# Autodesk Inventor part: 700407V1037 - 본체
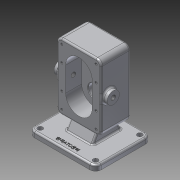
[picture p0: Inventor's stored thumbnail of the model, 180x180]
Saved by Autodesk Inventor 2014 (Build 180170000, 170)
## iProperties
Created: 2020-04
Part Number: 700407V1037 - 본체
Material: 알루미늄 6061
Document SubType Name: Modeling
Designer: kh
Density: 2.71 g/cm^3
Appearance: 알루미늄 - 평지
Mass: 1475.43 g
Surface Area: 815.025 cm^2
Volume: 544.438 cm^3
Author: kh
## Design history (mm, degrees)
sketch "스케치1"
  geometry: L1 (-50, 60)-(50, 60); L2 (50, 60)-(50, -60); L3 (50, -60)-(-50, -60); L4 (-50, -60)-(-50, 60); L5 (-50, 60)-(50, -60); L6 (50, 60)-(-50, -60); 1 further point
  constraints: 12 end point, 2 midpoint, 2 parallel, 1 horizontal, 1 perpendicular
  dimensions: "d0" = 100 distance of L2.end L3.end; "d1" = 120 distance of L1.end L2.end
extrude "돌출1" new body sketch "스케치1" stored distance "d2" = 10; taper "d3" = 0 deg
node "작업 평면2"
  node "작업 평면1"
sketch "스케치2"
  geometry: L1 (-120, 0)-(-120, -10) reference; L2 (0, 0)-(-120, 0) reference; L3 (0, 0)-(0, -10) reference; L4 (-120, -10)-(0, -10) reference; L5 (-100, 140)-(-20, 140); L6 (-20, 140)-(-20, 20); L7 (-20, 20)-(-100, 20); L8 (-100, 20)-(-100, 140); L9 (-20, 80)-(-100, 80); L10 (-60, 20)-(-60, 80); 1 further point
  constraints: 12 end point, 4 midpoint, 2 parallel, 1 horizontal, 1 perpendicular, 1 point on line
  dimensions: "d5" = 80 distance of L5.start L5.end; "d6" = 150 distance between parallel lines of L5 L4; "d7" = 90 distance between parallel lines of L9 L4
extrude "돌출2" join sketch "스케치2" distance "d8" = 53; taper "d9" = 0 deg
fillet "모깎기1" dims "d10" = 9
sketch "스케치4"
  geometry: L1 (20, 29)-(20, 91) reference; L2 (131, 20)-(29, 20) reference; L3 (140, 91)-(140, 29) reference; L4 (29, 100)-(131, 100) reference; L5 (102, 60)-(58, 60); L6 (102, 84)-(58, 84); L7 (58, 36)-(102, 36); L8 (20, 29)-(20, 91) reference; L9 (80, 100)-(80, 20); C1 r 12.5 at (102, 60); C2 r 12.5 at (58, 60); C3 r 8.5 at (102, 60); C4 r 8.5 at (58, 60); A1 r 9 centre (29, 91) between (29, 100) and (20, 91) reference; A2 r 9 centre (29, 29) between (20, 29) and (29, 20) reference; A3 r 9 centre (131, 29) between (131, 20) and (140, 29) reference; A4 r 9 centre (131, 91) between (140, 91) and (131, 100) reference; A5 r 24 centre (102, 60) between (102, 36) and (102, 84); A6 r 24 centre (58, 60) between (58, 84) and (58, 36); 3 further points
  constraints: 10 end point, 6 centre point, 5 coincident, 4 midpoint, 4 point on circle, 4 tangent, 1 parallel, 1 perpendicular
  dimensions: "d11" = 44 distance of L5.end L5.start; "d12" = 24 radius of A5; "d13" = 25 diameter of C1; "d14" = 25 diameter of C2; "d15" = 17 diameter of C3; "d16" = 17 diameter of C4
  node "투영된 루프5"
extrude "돌출3" cut sketch "스케치4" distance "d17" = 29; taper "d18" = 0 deg
extrude "돌출4" cut sketch "스케치4" distance "d19" = 44; taper "d20" = 0 deg
extrude "돌출5" cut sketch "스케치4" distance "d21" = 44; taper "d22" = 0 deg
sketch "스케치5"
  geometry: L1 (-29, 100)-(-131, 100) reference; L2 (-140, 91)-(-140, 29) reference; L3 (-131, 20)-(-29, 20) reference; L4 (-20, 29)-(-20, 91) reference; C1 r 8.5 at (-102, 60) reference; C2 r 14 at (-102, 60); C3 r 8.5 at (-102, 60); A1 r 9 centre (-29, 91) between (-20, 91) and (-29, 100) reference; A2 r 9 centre (-131, 91) between (-131, 100) and (-140, 91) reference; A3 r 9 centre (-131, 29) between (-140, 29) and (-131, 20) reference; A4 r 9 centre (-29, 29) between (-29, 20) and (-20, 29) reference; 1 further point
  constraints: 2 centre point, 2 coincident
  dimensions: "d23" = 28 diameter of C2; "d24" = 17 diameter of C3
  node "투영된 루프6"
extrude "돌출7" cut sketch "스케치5" stored distance "d27" = 7.3; taper "d28" = 0 deg
node "작업 평면5"
  node "작업 평면4"
sketch "스케치6"
  geometry: C1 r 12.5 at (38, 0) reference; C2 r 19 at (38, 0); C3 r 14 at (38, 0); 1 further point
  constraints: 2 centre point, 2 coincident
  dimensions: "d30" = 38 diameter of C2; "d31" = 28 diameter of C3
extrude "돌출8" join sketch "스케치6" distance "d32" = 17; taper "d33" = 0 deg
extrude "돌출9" cut sketch "스케치4" stored distance "d34" = 7.3; taper "d35" = 0 deg
node "작업 평면7"
  node "작업 평면6"
sketch "스케치9"
  geometry: L1 (53, -102)-(0, -102) reference; L2 (53, 0)-(53, -102) reference; L3 (0, 0)-(53, 0) reference; L4 (0, 0)-(0, -102) reference; L5 (70, -141)-(-30, -141) reference; C1 r 11 at (14, -51); 1 further point
  constraints: 1 centre point
  dimensions: "d37" = 22 diameter of C1; "d38" = 90 distance from line of C1.centre L5; "d39" = 14 distance from line of L4 C1.centre
extrude "돌출10" join sketch "스케치9" stored distance "d40" = 7.3; taper "d41" = 0 deg
node "작업 평면8"
sketch "스케치10"
  geometry: L1 (44, 16.5)-(44, 41.5) reference; L2 (0, 102)-(53, 102) reference; L3 (0, 102)-(0, 0) reference; L4 (53, 0)-(0, 0) reference; L5 (53, 102)-(53, 0) reference; L6 (-30, 141)-(70, 141) reference; C1 r 11 at (14, 51); 1 further point
  constraints: 1 centre point
  dimensions: "d43" = 22 diameter of C1; "d44" = 90 distance from line of C1.centre L6; "d45" = 14 distance from line of L3 C1.centre
extrude "돌출11" join sketch "스케치10" stored distance "d46" = 7.3; taper "d47" = 0 deg
sketch "스케치11"
  geometry: C1 r 11 at (0, 0) reference; 2 further points
  constraints: 1 coincident
hole "구멍1" sketch "스케치11" at (0, 0) diameter "d48" = 8.376; stored, may be unused: countersink angle "d52" = 90 deg, drill point angle "d54" = 118 deg; dims "d49" = 6, "d50" = 4, "d51" = 2, "d53" = 8
sketch "스케치12"
  geometry: L1 (58, 84)-(102, 84) reference; L2 (102, 36)-(58, 36) reference; L3 (20, 29)-(20, 91) reference; L4 (131, 20)-(29, 20) reference; L5 (140, 91)-(140, 29) reference; L6 (29, 100)-(131, 100) reference; L7 (126, 60)-(34, 60); L8 (80, 84)-(80, 36); A1 r 24 centre (58, 60) between (58, 84) and (58, 36) reference; A2 r 24 centre (102, 60) between (102, 36) and (102, 84) reference; A3 r 9 centre (29, 91) between (29, 100) and (20, 91) reference; A4 r 9 centre (29, 29) between (20, 29) and (29, 20) reference; A5 r 9 centre (131, 29) between (131, 20) and (140, 29) reference; A6 r 9 centre (131, 91) between (140, 91) and (131, 100) reference; 9 further points
  constraints: 4 coincident, 4 end point, 2 midpoint, 2 point on circle, 2 symmetric about line
  dimensions: "d57" = 29 distance of point (29, 29) point (58, 29); "d58" = 29 distance of point (58, 91) point (29, 91); "d60" = 62 distance of point (58, 29) point (58, 91); "d64" = 44 distance of point (58, 29) point (102, 29)
hole "구멍2" sketch "스케치12" at (131, 91), (131, 29), (29, 29), (29, 91), (58, 29), (58, 91), (102, 29), (102, 91) diameter "d65" = 4.134; stored, may be unused: countersink angle "d69" = 90 deg, drill point angle "d71" = 118 deg; dims "d66" = 10, "d67" = 4, "d68" = 2, "d70" = 12
node "작업 평면9"
sketch "스케치13"
  geometry: L1 (100, -10)-(0, -10) reference; L2 (0, -10)-(0, 0) reference; L3 (0, 0)-(100, 0) reference; L4 (100, 0)-(100, -10) reference; L5 (83, 110.5)-(74, 110.5) reference; L6 (74, 110.5)-(74, 114.5) reference; L7 (74, 114.5)-(59, 114.5) reference; L8 (59, 114.5)-(59, 126) reference; L9 (59, 126)-(30, 126) reference; L10 (30, 126)-(30, 140) reference; L11 (30, 140)-(83, 140) reference; L12 (83, 140)-(83, 121) reference; L13 (83, 121)-(100, 121) reference; L14 (100, 121)-(100, 83) reference; L15 (74, 93.5)-(83, 93.5) reference; L16 (100, 83)-(83, 83) reference; L17 (83, 83)-(83, 20) reference; L18 (83, 20)-(30, 20) reference; L19 (30, 20)-(30, 34) reference; L20 (30, 34)-(59, 34) reference; L21 (59, 34)-(59, 45.5) reference; L22 (59, 45.5)-(74, 45.5) reference; L23 (74, 45.5)-(74, 70.5) reference; L24 (74, 70.5)-(59, 70.5) reference; L25 (59, 70.5)-(59, 89.5) reference; L26 (59, 89.5)-(74, 89.5) reference; L27 (74, 89.5)-(74, 93.5) reference; L28 (30, 0)-(41.547, 20); L29 (83, 0)-(71.453, 20); L30 (41.547, 20)-(71.453, 20); L31 (30, 0)-(83, 0); L32 (83, 93.5)-(83, 110.5) reference; 1 further point
  constraints: 8 end point, 4 point on line, 1 collinear, 1 parallel
  dimensions: "d72" = 17 distance from line of L4 L29.start; "d73" = 53 distance of L28.start L29.start; "d74" = 60 deg angle of L29 L3; "d75" = 60 deg angle of L28 L3
extrude "돌출12" join sketch "스케치13" stored distance "d76" = 48; taper "d77" = 0 deg
fillet "모깎기2" dims "d78" = 10
sketch "스케치14"
  geometry: L1 (50, 50)-(50, -50) reference; L2 (40, -60)-(-40, -60) reference; L3 (-50, -50)-(-50, 50) reference; L4 (-40, 60)-(40, 60) reference; A1 r 10 centre (40, 50) between (50, 50) and (40, 60) reference; A2 r 10 centre (40, -50) between (40, -60) and (50, -50) reference; A3 r 10 centre (-40, -50) between (-50, -50) and (-40, -60) reference; A4 r 10 centre (-40, 50) between (-40, 60) and (-50, 50) reference; 5 further points
  constraints: 4 coincident
hole "구멍3" sketch "스케치14" at (-40, 50), (40, 50), (40, -50), (-40, -50) diameter "d79" = 9; stored, may be unused: countersink angle "d83" = 90 deg, drill point angle "d85" = 0 deg; dims "d80" = 10, "d81" = 4, "d82" = 2, "d84" = 12
sketch "스케치16"
  geometry: C1 r 14 at (0, 0) reference; C2 r 19 at (0, 0) reference; C3 r 14 at (0, 0); 1 further point
  constraints: 1 centre point, 1 coincident
  dimensions: "d86" = 28 diameter of C3
extrude "돌출13" cut sketch "스케치16" distance "d87" = 7.3; taper "d88" = 0 deg
sketch "스케치17"
  geometry: C1 r 8.5 at (0, 0) reference; C2 r 8.5 at (0, 0); 1 further point
  constraints: 1 centre point, 1 coincident
  dimensions: "d89" = 17 diameter of C2
extrude "돌출14" cut sketch "스케치17" stored distance "d90" = 7.3; taper "d91" = 0 deg
fillet "모깎기3" dims "d92" = 0.5
chamfer "모따기1" distance "d93" = 0.7; stored, may be unused: second distance "d94" = 2, angle "d95" = 30 deg
fillet "모깎기5" dims "d97" = 3
fillet "모깎기6" dims "d98" = 3
fillet "모깎기7" dims "d99" = 3
fillet "모깎기8" dims "d100" = 3
fillet "모깎기9" dims "d101" = 3
fillet "모깎기10" dims "d102" = 3
fillet "모깎기11" dims "d103" = 3
sketch "스케치18"
  geometry: L1 (-59.22, 36.577)-(-59.22, -36.577); L2 (-59.22, -36.577)-(-20.78, -36.577); L3 (-20.78, -36.577)-(-20.78, 36.577); L4 (-20.78, 36.577)-(-59.22, 36.577); L5 (-40, -36.577)-(-40, 36.577); L6 (-20.78, 0)-(-59.22, 0); L7 (40, 60)-(-40, 60) reference; L8 (-50, 50)-(-50, -50) reference; 1 further point
  constraints: 4 end point, 4 midpoint, 2 other
  dimensions: "d104" = 60 distance between parallel lines of L7 L6; "d105" = 10 distance between parallel lines of L5 L8
feature "엠보싱1" sketch "스케치18" dims "d106" = 0.5, "d107" = 0
chamfer "모따기2" distance "d108" = 1; stored, may be unused: second distance "d109" = 2, angle "d110" = 30 deg
node "솔리드1"
node "투영된 루프1"
node "투영된 루프7"
node "투영된 루프8"
node "투영된 루프9"
node "투영된 루프10"
node "투영된 루프11"
node "투영된 루프12"
node "투영된 루프13"
node "절단 모서리 투영1"
other parameters: "d29" = 17, "d36" = 8, "d42" = 8
